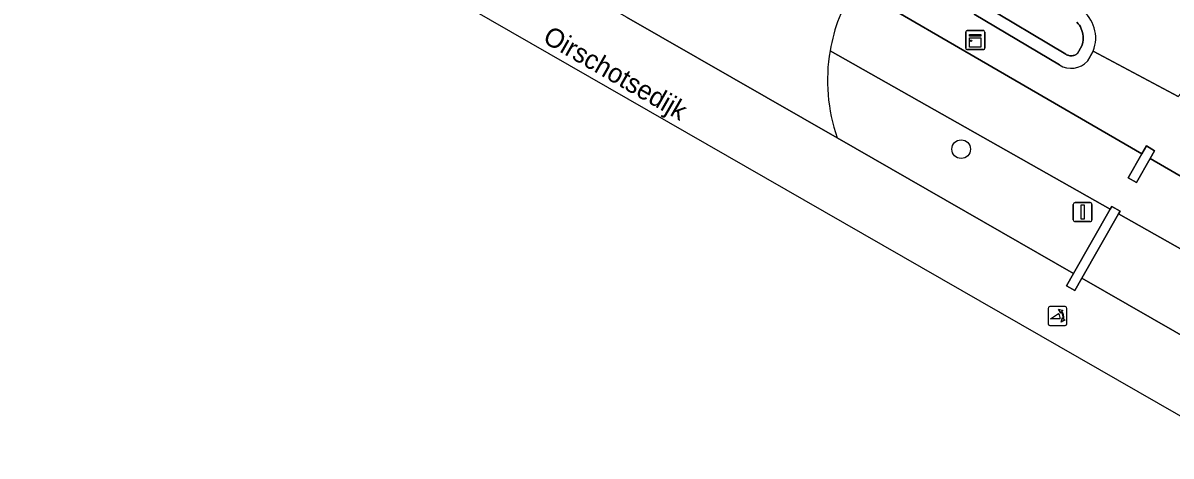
# Model space of a CAD drawing. Extents: x 157132 to 159279, y 384991 to 386650.
# Drawn here: x 158017.4 to 158077.8, y 385558.8 to 385581.6 of the extents above; entities that cross this region are included whole.
import ezdxf

# ---------------------------------------------------------------- set-up
doc = ezdxf.new("R2010")
doc.units = 0
for name, color, linetype in [('IMGEO_Berm_groen', 7, 'Continuous'), ('IMGEO_Boom', 7, 'Continuous'), ('IMGEO_Duiker', 7, 'Continuous'), ('IMGEO_Gemengd_bos', 7, 'Continuous'), ('IMGEO_Groenvoorziening', 7, 'Continuous'), ('IMGEO_Kast', 7, 'Continuous'), ('IMGEO_Lichtmast', 7, 'Continuous'), ('IMGEO_Muur', 7, 'Continuous'), ('IMGEO_Oever', 7, 'Continuous'), ('IMGEO_Openbare_ruimte_label', 7, 'Continuous'), ('IMGEO_Poller', 7, 'Continuous'), ('IMGEO_Rijbaan_lokaal_gesloten', 7, 'Continuous'), ('IMGEO_Voetpad_open', 7, 'Continuous'), ('IMGEO_Waterloop', 7, 'Continuous')]:
    doc.layers.add(name, color=color, linetype=linetype)

msp = doc.modelspace()

# ---------------------------------------------------------------- linework, layer by layer
at = {"layer": 'IMGEO_Berm_groen'}
for points in [[(158060.228, 385575.56), (158072.678, 385568.427), (158074.611, 385571.809), (158059.853, 385580.132)], [(158285.257, 385451.126), (158176.495, 385513.482), (158101.536, 385556.624), (158075.047, 385571.563), (158073.112, 385568.179), (158356.139, 385406.035), (158513.29, 385316.247)]]:
    msp.add_lwpolyline(points, dxfattribs=at)
msp.add_arc((158068.952, 385578.577), 9.231, 170.30186, 199.07606, dxfattribs=at)
at = {"layer": 'IMGEO_Boom'}
msp.add_circle((158066.758, 385574.962), 0.489, dxfattribs=at)
at = {"layer": 'IMGEO_Duiker'}
msp.add_lwpolyline([(158073.713, 385580.121), (158078.186, 385577.731)], dxfattribs=at)
at = {"layer": 'IMGEO_Gemengd_bos'}
msp.add_lwpolyline([(158073.713, 385580.121), (158078.186, 385577.731), (158078.266, 385577.827), (158078.361, 385577.924), (158078.464, 385578.011), (158078.575, 385578.089), (158078.692, 385578.157), (158078.815, 385578.213), (158078.942, 385578.259), (158079.073, 385578.293), (158079.206, 385578.316), (158079.341, 385578.326), (158079.477, 385578.324), (158079.611, 385578.31), (158079.744, 385578.285), (158079.874, 385578.247), (158080, 385578.198), (158127.699, 385551.206)], dxfattribs=at)
msp.add_arc((158071.987, 385580.803), 1.856, 338.44181, 54.86108, dxfattribs=at)
at = {"layer": 'IMGEO_Groenvoorziening'}
for points in [[(158066.272, 385587.531), (158069.869, 385592.715), (158068.119, 385593.764), (158063.347, 385586.486), (158063.017, 385586.603), (158061.887, 385584.846), (158061.143, 385583.492), (158076.275, 385574.719), (158076.517, 385575.142), (158076.946, 385574.878), (158076.71, 385574.467), (158105.423, 385557.822), (158183.671, 385513.054), (158236.145, 385482.72), (158260.678, 385468.751), (158287.398, 385454.035), (158354.571, 385415.192), (158364.636, 385409.372), (158500.664, 385331.766), (158520.349, 385320.633), (158522.865, 385324.358), (158522.182, 385324.766), (158520.938, 385323.509)], [(158071.934, 385579.394), (158067.445, 385582.062)], [(158078.186, 385577.731), (158073.713, 385580.121), (158073.412, 385579.592)]]:
    msp.add_lwpolyline(points, dxfattribs=at)
msp.add_arc((158072.553, 385580.391), 1.174, 238.1843, 317.07608, dxfattribs=at)
at = {"layer": 'IMGEO_Kast'}
for p, q in [((158067.001, 385580.274), (158067.001, 385581.115)), ((158067.001, 385581.115), (158067.001, 385580.274)), ((158067.076, 385581.199), (158067.917, 385581.199)), ((158067.917, 385581.199), (158067.076, 385581.199)), ((158068.001, 385581.124), (158068.001, 385580.283)), ((158068.001, 385580.283), (158068.001, 385581.124)), ((158067.926, 385580.199), (158067.085, 385580.199)), ((158067.085, 385580.199), (158067.926, 385580.199))]:
    msp.add_line(p, q, dxfattribs=at)
for points in [[(158067.196, 385580.989), (158067.796, 385580.989), (158067.796, 385580.904), (158067.196, 385580.904), (158067.196, 385580.989)], [(158067.196, 385580.814), (158067.796, 385580.814), (158067.796, 385580.325), (158067.196, 385580.325), (158067.196, 385580.814)]]:
    msp.add_lwpolyline(points, dxfattribs=at)
msp.add_circle((158067.28, 385580.663), 0.0377, dxfattribs=at)
for centre, start, end in [((158067.079, 385581.121), 92.4484, 184.28452), ((158067.079, 385581.121), 92.4484, 184.28452), ((158067.923, 385581.121), 2.4484, 94.28452), ((158067.923, 385581.121), 2.4484, 94.28452), ((158067.079, 385580.277), 182.4484, 274.28452), ((158067.079, 385580.277), 182.4484, 274.28452), ((158067.923, 385580.277), 272.4484, 4.28452), ((158067.923, 385580.277), 272.4484, 4.28452)]:
    msp.add_arc(centre, 0.0779, start, end, dxfattribs=at)
at = {"layer": 'IMGEO_Lichtmast'}
for p, q in [((158072.657, 385571.252), (158072.657, 385572.052)), ((158072.657, 385572.052), (158072.657, 385571.252)), ((158072.757, 385572.152), (158073.547, 385572.152)), ((158073.547, 385572.152), (158072.757, 385572.152)), ((158073.647, 385572.052), (158073.647, 385571.252)), ((158073.647, 385571.252), (158073.647, 385572.052)), ((158073.547, 385571.152), (158072.757, 385571.152)), ((158072.757, 385571.152), (158073.547, 385571.152))]:
    msp.add_line(p, q, dxfattribs=at)
msp.add_lwpolyline([(158073.077, 385572.027), (158073.227, 385572.027), (158073.227, 385571.277), (158073.077, 385571.277), (158073.077, 385572.027)], dxfattribs=at)
for centre, start, end in [((158072.757, 385572.052), 90, 180), ((158072.757, 385572.052), 90, 180), ((158073.547, 385572.052), 0, 90), ((158073.547, 385572.052), 360, 90), ((158072.757, 385571.252), 180, 270), ((158072.757, 385571.252), 180, 270), ((158073.547, 385571.252), 270, 0), ((158073.547, 385571.252), 270, 0)]:
    msp.add_arc(centre, 0.1, start, end, dxfattribs=at)
at = {"layer": 'IMGEO_Muur'}
for points in [[(158076.71, 385574.467), (158076.946, 385574.878), (158076.517, 385575.142), (158076.275, 385574.719), (158075.553, 385573.456), (158075.987, 385573.208)], [(158075.047, 385571.563), (158075.123, 385571.697), (158074.689, 385571.945), (158074.611, 385571.809), (158072.678, 385568.427), (158072.307, 385567.778), (158072.741, 385567.53), (158073.112, 385568.179)]]:
    msp.add_lwpolyline(points, close=True, dxfattribs=at)
at = {"layer": 'IMGEO_Oever'}
for points in [[(158072.853, 385581.637), (158072.921, 385581.56), (158072.982, 385581.477), (158073.036, 385581.39), (158073.082, 385581.299), (158073.12, 385581.204), (158073.15, 385581.106), (158073.172, 385581.006), (158073.185, 385580.904), (158073.189, 385580.802), (158073.184, 385580.699), (158073.171, 385580.598), (158073.149, 385580.498), (158073.119, 385580.4), (158072.889, 385579.995), (158072.854, 385579.968), (158072.817, 385579.944), (158072.779, 385579.923), (158072.738, 385579.906), (158072.697, 385579.892), (158072.654, 385579.882), (158072.611, 385579.875), (158072.567, 385579.872), (158072.523, 385579.873), (158072.479, 385579.877), (158072.436, 385579.885), (158072.394, 385579.897), (158072.352, 385579.912), (158072.313, 385579.93), (158072.275, 385579.952), (158067.791, 385582.617)], [(158067.445, 385582.062), (158071.934, 385579.394)], [(158073.412, 385579.592), (158073.713, 385580.121)]]:
    msp.add_lwpolyline(points, dxfattribs=at)
for centre, radius, start, end in [((158071.987, 385580.803), 1.856, 338.44181, 54.86108), ((158072.553, 385580.391), 1.174, 238.1843, 317.07608)]:
    msp.add_arc(centre, radius, start, end, dxfattribs=at)
at = {"layer": 'IMGEO_Poller'}
for p, q in [((158071.334, 385566.589), (158071.334, 385565.782)), ((158071.334, 385566.589), (158071.334, 385565.782)), ((158072.236, 385566.684), (158071.428, 385566.684)), ((158072.236, 385566.684), (158071.428, 385566.684)), ((158072.33, 385565.782), (158072.33, 385566.589)), ((158072.33, 385565.782), (158072.33, 385566.589)), ((158071.428, 385565.687), (158072.236, 385565.687)), ((158071.428, 385565.687), (158072.236, 385565.687))]:
    msp.add_line(p, q, dxfattribs=at)
for points in [[(158071.969, 385566.04), (158071.456, 385566.04), (158071.886, 385566.315)], [(158072.013, 385566.413), (158072.001, 385566.34), (158071.876, 385566.545)], [(158071.876, 385566.545), (158072.107, 385566.479), (158072.036, 385566.447)], [(158072.029, 385565.868), (158072.095, 385566.099), (158072.125, 385566.031)], [(158072.161, 385566.004), (158072.233, 385565.993), (158072.029, 385565.868)]]:
    msp.add_lwpolyline(points, dxfattribs=at)
for centre, radius, start, end in [((158071.428, 385566.589), 0.0946, 90, 180), ((158071.428, 385566.589), 0.0946, 90, 180), ((158071.641, 385566.09), 0.332, 351.32473, 42.4854), ((158071.655, 385566.1), 0.476, 351.75274, 41.16905), ((158071.655, 385566.1), 0.516, 349.35686, 42.29123), ((158072.236, 385566.589), 0.0946, 0, 90), ((158072.236, 385566.589), 0.0946, 0, 90), ((158071.428, 385565.782), 0.0946, 180, 270), ((158071.428, 385565.782), 0.0946, 180, 270), ((158072.236, 385565.782), 0.0946, 270, 0), ((158072.236, 385565.782), 0.0946, 270, 0)]:
    msp.add_arc(centre, radius, start, end, dxfattribs=at)
at = {"layer": 'IMGEO_Rijbaan_lokaal_gesloten'}
for points in [[(157962.149, 385631.647), (157960.386, 385628.605), (158092.746, 385552.638), (158517.188, 385311.578), (158723.574, 385194.362), (159060.524, 384999.643)], [(158513.29, 385316.247), (158356.139, 385406.035), (158073.112, 385568.179), (158072.741, 385567.53), (158072.307, 385567.778), (158072.678, 385568.427), (158060.228, 385575.56), (158049.13, 385581.903), (158016.204, 385600.757), (158013.742, 385602.423), (157999.976, 385610.05), (157979.215, 385622.102)], [(158049.13, 385581.903), (158060.228, 385575.56)]]:
    msp.add_lwpolyline(points, dxfattribs=at)
for centre, radius, start, end in [((158068.912, 385578.582), 9.19, 147.70462, 170.28893), ((158068.952, 385578.577), 9.231, 170.30186, 199.07606)]:
    msp.add_arc(centre, radius, start, end, dxfattribs=at)
at = {"layer": 'IMGEO_Voetpad_open'}
for points in [[(158287.398, 385454.035), (158260.678, 385468.751), (158236.145, 385482.72), (158183.671, 385513.054), (158105.423, 385557.822), (158076.71, 385574.467), (158075.987, 385573.208), (158075.553, 385573.456), (158076.275, 385574.719), (158061.143, 385583.492)], [(158059.853, 385580.132), (158074.611, 385571.809), (158074.689, 385571.945), (158075.123, 385571.697), (158075.047, 385571.563), (158101.536, 385556.624), (158176.495, 385513.482), (158285.257, 385451.126), (158352.993, 385412.497), (158354.571, 385415.192), (158287.398, 385454.035)]]:
    msp.add_lwpolyline(points, dxfattribs=at)
msp.add_arc((158068.912, 385578.582), 9.19, 147.70462, 170.28893, dxfattribs=at)
at = {"layer": 'IMGEO_Waterloop'}
msp.add_lwpolyline([(158067.791, 385582.617), (158072.275, 385579.952), (158072.313, 385579.93), (158072.352, 385579.912), (158072.394, 385579.897), (158072.436, 385579.885), (158072.479, 385579.877), (158072.523, 385579.873), (158072.567, 385579.872), (158072.611, 385579.875), (158072.654, 385579.882), (158072.697, 385579.892), (158072.738, 385579.906), (158072.779, 385579.923), (158072.817, 385579.944), (158072.854, 385579.968), (158072.889, 385579.995), (158073.119, 385580.4), (158073.149, 385580.498), (158073.171, 385580.598), (158073.184, 385580.699), (158073.189, 385580.802), (158073.185, 385580.904), (158073.172, 385581.006), (158073.15, 385581.106), (158073.12, 385581.204), (158073.082, 385581.299), (158073.036, 385581.39), (158072.982, 385581.477), (158072.921, 385581.56), (158072.853, 385581.637)], dxfattribs=at)

# ---------------------------------------------------------------- texts
at = {"layer": 'IMGEO_Openbare_ruimte_label'}
msp.add_text('Oirschotsedijk', height=1, rotation=330.12718, dxfattribs=at).set_placement((158044.669, 385580.624))

doc.saveas('drawing.dxf')
